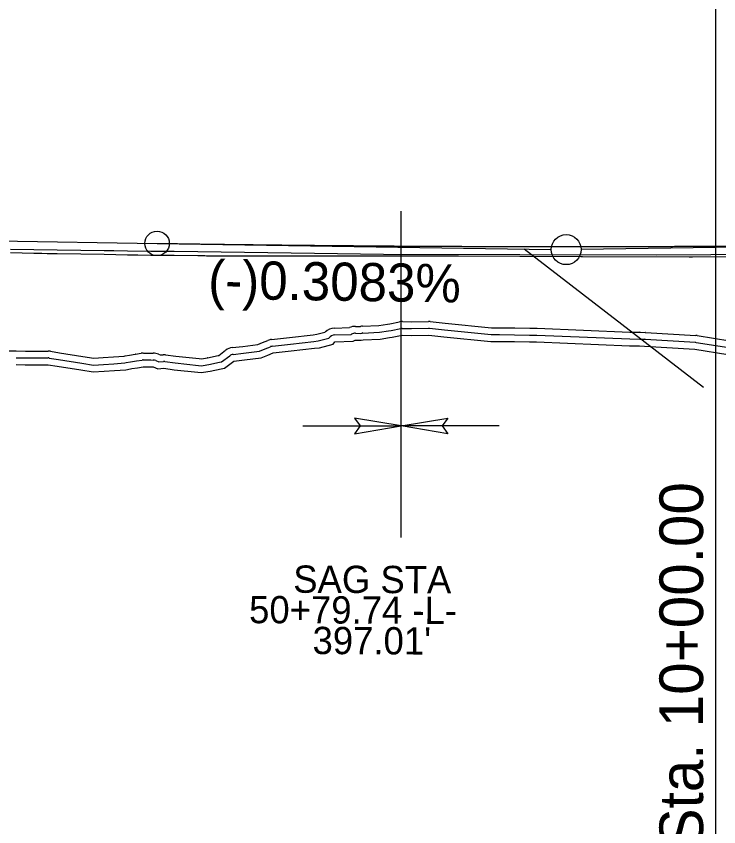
# Model space of a CAD drawing. Extents: x 1625686 to 1640492, y 1161393 to 1175642.
# Drawn here: x 1634213.5 to 1634342.3, y 1175041.7 to 1175190.2 of the extents above; entities that cross this region are included whole.
import ezdxf

# ---------------------------------------------------------------- set-up
doc = ezdxf.new("R2010")
doc.units = 0
for name, color, linetype in [('Exist Vertical Profile Ground Line', 7, 'Continuous'), ('Prop PFL Text', 7, 'Continuous'), ('Prop Plan Preparation Sag', 7, 'Continuous'), ('Prop Vertical Profile Curve Label', 7, 'Continuous'), ('Prop Vertical Profile Grade', 7, 'Continuous'), ('Prop Vertical Profile Grade Label', 7, 'Continuous'), ('Prop VPI Label', 7, 'Continuous'), ('Scratch_Level_1', 7, 'Continuous'), ('Scratch_Level_3', 7, 'Continuous'), ('Scratch_Level_5', 7, 'Continuous')]:
    doc.layers.add(name, color=color, linetype=linetype)

msp = doc.modelspace()

# ---------------------------------------------------------------- linework, layer by layer
at = {"layer": 'Exist Vertical Profile Ground Line'}
msp.add_lwpolyline([(1634212.46, 1175146.89), (1634216.74, 1175146.81), (1634218.21, 1175146.79), (1634219.2, 1175146.76), (1634221.03, 1175146.73), (1634225.32, 1175146.66), (1634229.61, 1175146.58), (1634233.89, 1175146.51), (1634235.09, 1175146.49), (1634235.82, 1175146.47), (1634238.18, 1175146.45), (1634242.47, 1175146.41), (1634246.76, 1175146.37), (1634247.71, 1175146.36), (1634248.09, 1175146.34), (1634248.4, 1175146.32), (1634251.04, 1175146.32), (1634255.33, 1175146.32), (1634259.62, 1175146.32), (1634263.91, 1175146.31), (1634268.19, 1175146.31), (1634273.27, 1175146.3), (1634292.18, 1175146.29), (1634294.57, 1175146.29), (1634317.01, 1175146.21), (1634317.32, 1175146.21), (1634336.88, 1175146.14), (1634337.45, 1175146.14), (1634362, 1175146.32)], dxfattribs=at)
at = {"layer": 'Prop PFL Text'}
msp.add_line((1634341.72, 1174977.9), (1634341.72, 1175146.38), dxfattribs=at)
at = {"layer": 'Prop Plan Preparation Sag'}
for p, q in [((1634284.05, 1175094.7), (1634284.05, 1175154.46)), ((1634266.05, 1175115.13), (1634284.05, 1175115.13)), ((1634302.05, 1175115.13), (1634284.05, 1175115.13))]:
    msp.add_line(p, q, dxfattribs=at)
for points in [[(1634275.49, 1175113.71), (1634284.05, 1175115.13), (1634275.49, 1175116.56), (1634276.55, 1175115.13)], [(1634292.62, 1175113.71), (1634284.05, 1175115.13), (1634292.62, 1175116.56), (1634291.55, 1175115.13)]]:
    msp.add_lwpolyline(points, close=True, dxfattribs=at)
at = {"layer": 'Prop Vertical Profile Curve Label'}
msp.add_circle((1634239.31, 1175148.59), 2.25, dxfattribs=at)
at = {"layer": 'Prop Vertical Profile Grade'}
msp.add_line((1633889.31, 1175153.99), (1634239.31, 1175148.59), dxfattribs=at)
msp.add_spline([(1634239.31, 1175148.59), (1634242.31, 1175148.55), (1634245.31, 1175148.5), (1634248.31, 1175148.46), (1634251.31, 1175148.42), (1634254.31, 1175148.38), (1634257.31, 1175148.35), (1634260.31, 1175148.31), (1634263.31, 1175148.28), (1634266.31, 1175148.25), (1634269.31, 1175148.22), (1634272.31, 1175148.19), (1634275.31, 1175148.17), (1634278.31, 1175148.15), (1634281.31, 1175148.12), (1634284.31, 1175148.1), (1634287.31, 1175148.09), (1634290.31, 1175148.07), (1634293.31, 1175148.06), (1634296.31, 1175148.04), (1634299.31, 1175148.03), (1634302.31, 1175148.02), (1634305.31, 1175148.02), (1634308.31, 1175148.01), (1634311.31, 1175148.01), (1634314.31, 1175148.01), (1634317.31, 1175148.01), (1634320.31, 1175148.01), (1634323.31, 1175148.01), (1634326.31, 1175148.02), (1634329.31, 1175148.03), (1634332.31, 1175148.04), (1634335.31, 1175148.05), (1634338.31, 1175148.06), (1634341.31, 1175148.08), (1634344.31, 1175148.09), (1634347.31, 1175148.11), (1634350.31, 1175148.13), (1634353.31, 1175148.15), (1634356.31, 1175148.18), (1634359.31, 1175148.2), (1634362.31, 1175148.23), (1634365.31, 1175148.26), (1634368.31, 1175148.29), (1634371.31, 1175148.32), (1634374.31, 1175148.36), (1634377.31, 1175148.4), (1634380.31, 1175148.43), (1634383.31, 1175148.48), (1634386.31, 1175148.52), (1634389.31, 1175148.56)], degree=3, dxfattribs=at)
at = {"layer": 'Prop VPI Label'}
for p, q in [((1634239.31, 1175148.59), (1634311.56, 1175147.48)), ((1634389.31, 1175148.56), (1634317.06, 1175147.48)), ((1634339.49, 1175122.17), (1634306.64, 1175147.55))]:
    msp.add_line(p, q, dxfattribs=at)
msp.add_circle((1634314.31, 1175147.44), 2.75, dxfattribs=at)
at = {"layer": 'Scratch_Level_1'}
for p, q in [((1634271.84, 1175133.07), (1634274.58, 1175133.15)), ((1634327.89, 1175132.31), (1634328.81, 1175132.26)), ((1634328.84, 1175132.26), (1634338.07, 1175131.7)), ((1634327.83, 1175131.06), (1634328.75, 1175131.01)), ((1634328.77, 1175131.01), (1634337.99, 1175130.46)), ((1634217.1, 1175128.86), (1634217.63, 1175128.86)), ((1634217.65, 1175128.86), (1634219.38, 1175128.85)), ((1634234.26, 1175128.1), (1634235.32, 1175128.28)), ((1634235.34, 1175128.28), (1634236.38, 1175128.45)), ((1634217.1, 1175127.61), (1634217.63, 1175127.61)), ((1634217.64, 1175127.61), (1634219.37, 1175127.6)), ((1634234.47, 1175126.87), (1634235.53, 1175127.04)), ((1634235.54, 1175127.04), (1634236.58, 1175127.21))]:
    msp.add_line(p, q, dxfattribs=at)
for points in [[(1634276.98, 1175133.41), (1634279.99, 1175133.54), (1634281.53, 1175133.78), (1634281.98, 1175133.86), (1634283.73, 1175134.21)], [(1634284.28, 1175134.26), (1634285.97, 1175134.22), (1634289.07, 1175134.27)], [(1634289.37, 1175134.26), (1634292.12, 1175133.97), (1634300.61, 1175133.13), (1634302.07, 1175133.11), (1634304.83, 1175133.09)], [(1634260.31, 1175130.99), (1634263.62, 1175131.37), (1634267.91, 1175131.85), (1634268.63, 1175131.94), (1634270.1, 1175132.3)], [(1634275.71, 1175133.38), (1634276.52, 1175133.35), (1634276.6, 1175133.37)], [(1634277.03, 1175132.16), (1634280.12, 1175132.3), (1634281.73, 1175132.55), (1634282.2, 1175132.63), (1634283.98, 1175132.98)], [(1634284.25, 1175133.01), (1634285.97, 1175132.97), (1634289.09, 1175133.02)], [(1634289.24, 1175133.02), (1634292, 1175132.73), (1634300.54, 1175131.88), (1634302.06, 1175131.86), (1634304.83, 1175131.84)], [(1634304.87, 1175133.09), (1634307.64, 1175133.04), (1634308.93, 1175133.02)], [(1634308.99, 1175133.02), (1634325.99, 1175132.33), (1634327.81, 1175132.31)], [(1634253.09, 1175129.48), (1634255.03, 1175129.71), (1634257.77, 1175130.05), (1634258.66, 1175130.41), (1634259.63, 1175130.82)], [(1634260.45, 1175129.75), (1634263.77, 1175130.12), (1634268.05, 1175130.61), (1634268.85, 1175130.7), (1634270.82, 1175131.19), (1634270.87, 1175131.25)], [(1634271.88, 1175131.82), (1634274.92, 1175131.91), (1634274.96, 1175131.94)], [(1634275.67, 1175132.13), (1634276.63, 1175132.1), (1634276.84, 1175132.14)], [(1634304.84, 1175131.84), (1634307.61, 1175131.79), (1634308.91, 1175131.77)], [(1634308.94, 1175131.77), (1634325.95, 1175131.08), (1634327.79, 1175131.06)], [(1634338.31, 1175131.68), (1634344.29, 1175130.73), (1634349.52, 1175130.12), (1634354.62, 1175130.51)], [(1634253.24, 1175128.24), (1634255.18, 1175128.47), (1634258.09, 1175128.82), (1634259.14, 1175129.26), (1634260.11, 1175129.66)], [(1634338.11, 1175130.44), (1634344.12, 1175129.49), (1634349.49, 1175128.86), (1634354.72, 1175129.27)], [(1634207.51, 1175128.94), (1634208.21, 1175128.92), (1634209.6, 1175128.9), (1634211.59, 1175128.88), (1634212.47, 1175128.88), (1634213.5, 1175128.88)], [(1634213.51, 1175128.88), (1634215.17, 1175128.86), (1634216.75, 1175128.86), (1634217.1, 1175128.86)], [(1634219.76, 1175128.81), (1634221.43, 1175128.54), (1634225.72, 1175127.85), (1634227.71, 1175127.54), (1634229.44, 1175127.65), (1634231.33, 1175127.78), (1634233.27, 1175127.93), (1634233.47, 1175127.96), (1634234.24, 1175128.1)], [(1634236.8, 1175128.48), (1634238.2, 1175128.47), (1634238.62, 1175128.46)], [(1634239.56, 1175128.28), (1634239.86, 1175128.15), (1634240.44, 1175128.18)], [(1634240.88, 1175128.17), (1634242.76, 1175127.93), (1634247.02, 1175127.47), (1634247.44, 1175127.43), (1634248.19, 1175127.54), (1634248.51, 1175127.61)], [(1634248.55, 1175127.62), (1634250.54, 1175128.03), (1634250.61, 1175128.04), (1634251.89, 1175129)], [(1634248.8, 1175126.39), (1634250.79, 1175126.81), (1634251.13, 1175126.88), (1634252.64, 1175128)], [(1634213.5, 1175127.63), (1634215.16, 1175127.61), (1634216.75, 1175127.61), (1634217.1, 1175127.61)], [(1634219.56, 1175127.58), (1634221.23, 1175127.31), (1634225.52, 1175126.62), (1634227.65, 1175126.28), (1634229.52, 1175126.4), (1634231.42, 1175126.53), (1634233.42, 1175126.69), (1634233.68, 1175126.73), (1634234.46, 1175126.87)], [(1634236.79, 1175127.23), (1634238.19, 1175127.22), (1634238.61, 1175127.21)], [(1634239.08, 1175127.12), (1634239.65, 1175126.89), (1634240.5, 1175126.93)], [(1634240.73, 1175126.93), (1634242.61, 1175126.68), (1634246.89, 1175126.23), (1634247.47, 1175126.17), (1634248.42, 1175126.31), (1634248.78, 1175126.39)]]:
    msp.add_lwpolyline(points, dxfattribs=at)
for centre, radius, start, end in [((1634284.22, 1175131.76), 2.5, 88.6806, 101.2879), ((1634289.11, 1175131.77), 2.5, 84.0361, 91.0172), ((1634271.92, 1175130.57), 2.5, 91.6323, 136.4335), ((1634275.63, 1175130.88), 2.5, 88.0965, 114.7448), ((1634277.09, 1175130.92), 2.5, 92.5023, 101.2324), ((1634284.22, 1175131.76), 1.25, 88.6806, 101.2879), ((1634289.11, 1175131.77), 1.25, 84.0361, 91.0172), ((1634304.82, 1175130.59), 2.5, 88.9421, 89.6981), ((1634308.89, 1175130.52), 2.5, 87.6899, 89.0176), ((1634327.77, 1175129.81), 2.5, 87.3258, 89.272), ((1634328.69, 1175129.77), 2.5, 86.5397, 87.3258), ((1634260.59, 1175128.51), 2.5, 96.458, 112.5695), ((1634271.92, 1175130.57), 1.25, 91.6323, 147.0323), ((1634275.63, 1175130.88), 1.25, 88.0965, 122.2353), ((1634277.09, 1175130.92), 1.25, 92.5023, 101.2324), ((1634304.82, 1175130.59), 1.25, 88.9421, 89.6981), ((1634308.89, 1175130.52), 1.25, 87.6899, 89.0176), ((1634327.77, 1175129.81), 1.25, 87.3258, 89.272), ((1634328.69, 1175129.77), 1.25, 86.5397, 87.3258), ((1634337.91, 1175129.21), 2.5, 81.0194, 86.5397), ((1634253.39, 1175127), 2.5, 96.8626, 126.7078), ((1634260.59, 1175128.51), 1.25, 96.458, 112.5695), ((1634337.91, 1175129.21), 1.25, 81.0194, 86.5397), ((1634213.49, 1175126.38), 2.5, 89.5718, 89.8079), ((1634217.1, 1175126.36), 2.5, 89.9589, 90.0146), ((1634217.63, 1175126.36), 2.5, 89.5159, 89.9589), ((1634219.36, 1175126.35), 2.5, 80.7935, 89.5159), ((1634234.67, 1175125.63), 2.5, 99.4246, 99.8362), ((1634235.73, 1175125.81), 2.5, 99.1158, 99.4246), ((1634236.78, 1175125.98), 2.5, 89.59, 99.1158), ((1634238.61, 1175125.96), 2.5, 67.6171, 89.6196), ((1634240.57, 1175125.69), 2.5, 82.7457, 93.0515), ((1634253.39, 1175127), 1.25, 96.8626, 126.7078), ((1634213.49, 1175126.38), 1.25, 89.5718, 89.8079), ((1634217.1, 1175126.36), 1.25, 89.9589, 90.0146), ((1634217.63, 1175126.36), 1.25, 89.5159, 89.9589), ((1634219.36, 1175126.35), 1.25, 80.7935, 89.5159), ((1634234.67, 1175125.63), 1.25, 99.4246, 99.8362), ((1634235.73, 1175125.81), 1.25, 99.1158, 99.4246), ((1634236.78, 1175125.98), 1.25, 89.59, 99.1158), ((1634238.61, 1175125.96), 1.25, 67.6171, 89.6196), ((1634240.57, 1175125.69), 1.25, 82.7457, 93.0515), ((1634249.05, 1175125.17), 2.5, 101.6943, 102.6083), ((1634249.05, 1175125.17), 1.25, 101.6943, 102.6083)]:
    msp.add_arc(centre, radius, start, end, dxfattribs=at)
at = {"layer": 'Scratch_Level_3'}
for points in [[(1630204.31, 1174910.79), (1634341.72, 1174910.79), (1634341.72, 1175362.47)], [(1634212.46, 1175147.51), (1634216.74, 1175147.45), (1634221.03, 1175147.4), (1634225.32, 1175147.34), (1634229.61, 1175147.28), (1634230.81, 1175147.27), (1634231.42, 1175147.26), (1634233.89, 1175147.23), (1634238.18, 1175147.18), (1634242.47, 1175147.13), (1634246.76, 1175147.08), (1634251.04, 1175147.02), (1634255.33, 1175146.97), (1634259.62, 1175146.91), (1634263.91, 1175146.86), (1634268.19, 1175146.8), (1634280.81, 1175146.63), (1634330.81, 1175146.46), (1634380.81, 1175146.81)]]:
    msp.add_lwpolyline(points, dxfattribs=at)
at = {"layer": 'Scratch_Level_5'}
msp.add_lwpolyline([(1634213.49, 1175126.38), (1634215.16, 1175126.36), (1634216.74, 1175126.36), (1634217.1, 1175126.36), (1634217.63, 1175126.36), (1634219.36, 1175126.35), (1634221.03, 1175126.08), (1634225.32, 1175125.39), (1634227.59, 1175125.02), (1634229.61, 1175125.16), (1634231.51, 1175125.28), (1634233.57, 1175125.44), (1634233.89, 1175125.5), (1634234.67, 1175125.63), (1634235.73, 1175125.81), (1634236.78, 1175125.98), (1634238.18, 1175125.97), (1634238.61, 1175125.96), (1634239.43, 1175125.62), (1634240.57, 1175125.69), (1634242.47, 1175125.44), (1634246.76, 1175124.99), (1634247.49, 1175124.91), (1634248.64, 1175125.08), (1634249.05, 1175125.17), (1634251.04, 1175125.58), (1634251.66, 1175125.71), (1634253.39, 1175127), (1634255.33, 1175127.23), (1634258.41, 1175127.6), (1634259.62, 1175128.1), (1634260.59, 1175128.51), (1634263.91, 1175128.88), (1634268.19, 1175129.37), (1634269.07, 1175129.47), (1634271.6, 1175130.09), (1634271.92, 1175130.57), (1634275.29, 1175130.67), (1634275.63, 1175130.88), (1634276.73, 1175130.84), (1634277.09, 1175130.92), (1634280.24, 1175131.05), (1634281.93, 1175131.31), (1634282.43, 1175131.4), (1634284.22, 1175131.76), (1634285.97, 1175131.72), (1634289.11, 1175131.77), (1634291.87, 1175131.48), (1634300.47, 1175130.63), (1634302.05, 1175130.61), (1634304.82, 1175130.59), (1634307.59, 1175130.54), (1634308.89, 1175130.52), (1634325.92, 1175129.83), (1634327.77, 1175129.81), (1634328.69, 1175129.77), (1634337.91, 1175129.21), (1634343.95, 1175128.25)], dxfattribs=at)

# ---------------------------------------------------------------- texts
at = {"layer": 'Prop PFL Text'}
msp.add_text('POT -DR2- Sta. 10+00.00', height=8, rotation=90, dxfattribs=at).set_placement((1634339.41, 1174981.45))
at = {"layer": 'Prop Plan Preparation Sag'}
for s, p in [('SAG STA', (1634264.27, 1175084.57)), ('50+79.74 -L-', (1634256.18, 1175078.99)), ("397.01'", (1634267.81, 1175073.33))]:
    msp.add_text(s, height=5, rotation=359.7547, dxfattribs=at).set_placement(p)
at = {"layer": 'Prop Vertical Profile Grade Label'}
msp.add_text('(-)0.3083%', height=7, rotation=359.1169, dxfattribs=at).set_placement((1634248.65, 1175138.45))

doc.saveas('drawing.dxf')
